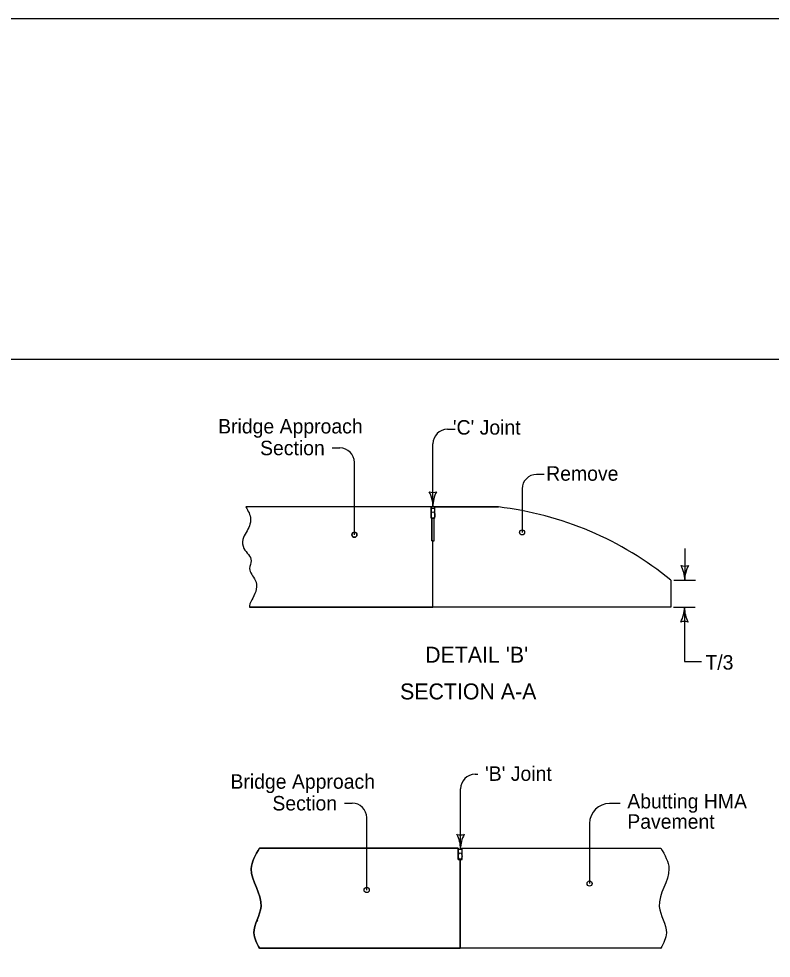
# Model space of a CAD drawing. Extents: x -2135039 to -2131695, y -2139150 to -2136566.
# Drawn here: x -2133963 to -2132926, y -2137862 to -2136566 of the extents above; entities that cross this region are included whole.
import ezdxf

# ---------------------------------------------------------------- set-up
doc = ezdxf.new("R2010")
doc.units = 0
for name, color, linetype in [('dsnCellElements', 7, 'Continuous'), ('dsnDOTLogo', 7, 'Continuous'), ('Level 1', 7, 'Continuous'), ('Level 2', 7, 'Continuous'), ('Level 3', 7, 'Continuous')]:
    doc.layers.add(name, color=color, linetype=linetype)

msp = doc.modelspace()

# ---------------------------------------------------------------- linework, layer by layer
at = {"layer": 'dsnCellElements'}
for centre in [(-2133483.7, -2137768.3), (-2133176.4, -2137759.4)]:
    msp.add_circle(centre, 3.54, dxfattribs=at)
at = {"layer": 'dsnDOTLogo'}
msp.add_lwpolyline([(-2135038.9, -2139150.4), (-2131694.9, -2139150.4), (-2131694.9, -2136566.4), (-2135038.9, -2136566.4)], close=True, dxfattribs=at)
at = {"layer": 'Level 1'}
msp.add_lwpolyline([(-2134934.4, -2137035.9), (-2131799.4, -2137035.9), (-2131799.4, -2139045.9), (-2134934.4, -2139045.9)], close=True, dxfattribs=at)
at = {"layer": 'Level 2'}
for p, q in [((-2133372.4, -2137132.8), (-2133361.7, -2137132.8)), ((-2133392.4, -2137239.3), (-2133392.4, -2137152.8)), ((-2133531.5, -2137158.4), (-2133520.7, -2137158.4)), ((-2133500.7, -2137278.2), (-2133500.7, -2137178.4)), ((-2133238.9, -2137195), (-2133249.4, -2137195)), ((-2133269.4, -2137215), (-2133269.4, -2137274.9)), ((-2133302.1, -2137239.9), (-2133650.3, -2137239.9)), ((-2133395, -2137239.9), (-2133395, -2137255.5)), ((-2133395, -2137241.5), (-2133389.7, -2137241.5)), ((-2133389.7, -2137255.5), (-2133389.7, -2137239.9)), ((-2133389.7, -2137239.9), (-2133302.1, -2137239.9)), ((-2133395, -2137255.5), (-2133390.6, -2137255.5)), ((-2133394.1, -2137255.5), (-2133395, -2137255.5)), ((-2133394.1, -2137255.5), (-2133394.1, -2137286.5)), ((-2133394.1, -2137286.5), (-2133394.1, -2137255.5)), ((-2133389.7, -2137255.5), (-2133390.6, -2137255.5)), ((-2133390.6, -2137286.5), (-2133390.6, -2137255.5)), ((-2133394.1, -2137286.5), (-2133392.3, -2137286.5)), ((-2133392.3, -2137286.5), (-2133394.1, -2137286.5)), ((-2133392.3, -2137378.2), (-2133392.3, -2137286.5)), ((-2133392.3, -2137286.5), (-2133390.6, -2137286.5)), ((-2133045.2, -2137297.1), (-2133045.2, -2137340.9)), ((-2133064.2, -2137340.9), (-2133064.2, -2137378.3)), ((-2133060.2, -2137340.9), (-2133030.2, -2137340.9)), ((-2133396.5, -2137378.2), (-2133645.1, -2137378.2)), ((-2133645.1, -2137378.2), (-2133396.5, -2137378.2)), ((-2133064.2, -2137378.2), (-2133396.5, -2137378.2)), ((-2133396.5, -2137378.2), (-2133392.3, -2137378.2)), ((-2133396.5, -2137378.2), (-2133392.3, -2137378.2)), ((-2133060.6, -2137378.3), (-2133030.6, -2137378.3)), ((-2133045.6, -2137378.3), (-2133045.6, -2137452.9)), ((-2133045.6, -2137452.9), (-2133022.1, -2137452.9)), ((-2133334.3, -2137608.7), (-2133330.4, -2137608.7)), ((-2133354.3, -2137711.8), (-2133354.3, -2137628.7)), ((-2133514.5, -2137648.5), (-2133503.7, -2137648.5)), ((-2133134.1, -2137649), (-2133148.7, -2137649)), ((-2133483.7, -2137768.3), (-2133483.7, -2137668.5)), ((-2133176.4, -2137676.6), (-2133176.4, -2137759.4)), ((-2133631.4, -2137710.4), (-2133357.4, -2137710.4)), ((-2133595.4, -2137710.4), (-2133631.4, -2137710.4)), ((-2133357.4, -2137710.4), (-2133357.4, -2137726)), ((-2133357.4, -2137712.1), (-2133352.2, -2137712.1)), ((-2133352.2, -2137726), (-2133352.2, -2137710.4)), ((-2133352.2, -2137710.4), (-2133078.2, -2137710.4)), ((-2133352.2, -2137711.7), (-2133351, -2137710.4)), ((-2133357.4, -2137726), (-2133354.8, -2137726)), ((-2133354.8, -2137726), (-2133357.4, -2137726)), ((-2133354.8, -2137726), (-2133352.2, -2137726)), ((-2133354.8, -2137848.7), (-2133354.8, -2137726)), ((-2133354.8, -2137726), (-2133354.8, -2137848.7)), ((-2133354.8, -2137805.1), (-2133354.8, -2137726)), ((-2133354.8, -2137726), (-2133354.8, -2137726)), ((-2133354.8, -2137831.7), (-2133354.8, -2137805.1)), ((-2133354.8, -2137805.1), (-2133354.8, -2137805.1)), ((-2133354.8, -2137831.7), (-2133354.8, -2137831.7)), ((-2133354.8, -2137848.7), (-2133631.4, -2137848.7)), ((-2133078.2, -2137848.7), (-2133354.8, -2137848.7)), ((-2133078.5, -2137848.7), (-2133077.8, -2137848))]:
    msp.add_line(p, q, dxfattribs=at)
for points in [[(-2133395, -2137239.9), (-2133500.7, -2137239.9), (-2133650.3, -2137239.9)], [(-2133395, -2137255.5), (-2133395, -2137241.5), (-2133395, -2137239.9)], [(-2133500.7, -2137274.7), (-2133500.7, -2137274.7)], [(-2133392.3, -2137378.2), (-2133392.3, -2137376.7), (-2133392.3, -2137368.3), (-2133392.3, -2137359.8), (-2133392.3, -2137351.3), (-2133392.3, -2137342.8), (-2133392.3, -2137334.3), (-2133392.3, -2137325.8), (-2133392.3, -2137317.3), (-2133392.3, -2137308.9), (-2133392.3, -2137300.4), (-2133392.3, -2137291.9), (-2133392.3, -2137286.5)], [(-2133595.4, -2137710.4), (-2133595.4, -2137710.4)], [(-2133546.9, -2137710.4), (-2133551.4, -2137710.4), (-2133593.7, -2137710.4)], [(-2133593.7, -2137710.4), (-2133593.7, -2137710.4)], [(-2133546.9, -2137710.4), (-2133546.9, -2137710.4)], [(-2133357.4, -2137710.4), (-2133414.3, -2137710.4), (-2133483.7, -2137710.4), (-2133545.2, -2137710.4)], [(-2133545.2, -2137710.4), (-2133545.2, -2137710.4)], [(-2133414.3, -2137710.4), (-2133414.3, -2137710.7)], [(-2133357.4, -2137726), (-2133357.4, -2137712.1), (-2133357.4, -2137710.4)], [(-2133354.8, -2137805.1), (-2133354.8, -2137805.1)], [(-2133354.8, -2137805.1), (-2133354.8, -2137805.1)], [(-2133354.8, -2137805.1), (-2133354.8, -2137805.1)], [(-2133354.8, -2137805.1), (-2133354.8, -2137805.1)], [(-2133633.8, -2137810.3), (-2133636.2, -2137812.9)], [(-2133354.8, -2137831.7), (-2133354.8, -2137831.7)], [(-2133354.8, -2137831.7), (-2133354.8, -2137831.7)], [(-2133354.8, -2137848), (-2133354.8, -2137848), (-2133354.8, -2137831.7)], [(-2133354.8, -2137831.7), (-2133354.8, -2137831.7)], [(-2133354.8, -2137831.7), (-2133354.8, -2137831.7)], [(-2133631.4, -2137848.7), (-2133415, -2137848.7), (-2133356.3, -2137848.7)], [(-2133356.3, -2137848.7), (-2133356.3, -2137848.7)]]:
    msp.add_lwpolyline(points, dxfattribs=at)
for centre, radius in [((-2133269.4, -2137274.9), 3.5), ((-2133500.7, -2137278.2), 3.5), ((-2133483.7, -2137768.3), 3.54)]:
    msp.add_circle(centre, radius, dxfattribs=at)
for centre, radius, start, end in [((-2133372.4, -2137152.8), 20, 90, 180), ((-2133520.7, -2137178.4), 20, 0, 90), ((-2133249.4, -2137215), 20, 90, 180), ((-2133392.4, -2137203.1), 16.7, 252.2666, 287.7333), ((-2133435.6, -2137239.3), 43.2, 360, 28.0725), ((-2133349.3, -2137239.3), 43.2, 151.9275, 180), ((-2133355.5, -2137696.2), 459.4, 50.6582, 83.3286), ((-2133500.7, -2137278.2), 3.5, 90.0901, 90), ((-2133045.2, -2137304.7), 16.7, 252.2666, 287.7333), ((-2133088.4, -2137340.9), 43.2, 360, 28.0725), ((-2133002, -2137340.9), 43.2, 151.9275, 180), ((-2133088.8, -2137378.3), 43.2, 331.9275, 360), ((-2133002.4, -2137378.3), 43.2, 180, 208.0725), ((-2133045.6, -2137414.5), 16.7, 72.2666, 107.7334), ((-2133334.3, -2137628.7), 20, 90, 180), ((-2133503.7, -2137668.5), 20, 0, 90), ((-2133148.7, -2137676.6), 27.7, 90, 180), ((-2133354.3, -2137675.6), 16.7, 252.2666, 287.7333), ((-2133397.5, -2137711.8), 43.2, 360, 28.0725), ((-2133311.1, -2137711.8), 43.2, 151.9275, 180)]:
    msp.add_arc(centre, radius, start, end, dxfattribs=at)
for centre in [(-2133392.3, -2137251.2), (-2133354.8, -2137721.6)]:
    msp.add_ellipse(centre, major_axis=(0, 4.37), ratio=0.6, dxfattribs=at)
for points in [[(-2133650.3, -2137239.9), (-2133643.7, -2137256.4), (-2133649.8, -2137274.9), (-2133654.4, -2137284.8), (-2133652.9, -2137297.1), (-2133642.9, -2137314), (-2133645.2, -2137324.8), (-2133637.3, -2137340.9), (-2133640.6, -2137365.5), (-2133645.2, -2137376.2), (-2133645.1, -2137378.2)], [(-2133650.3, -2137239.9), (-2133643.7, -2137256.4), (-2133649.8, -2137274.9), (-2133654.4, -2137284.8), (-2133652.9, -2137297.1), (-2133642.9, -2137314), (-2133645.2, -2137324.8), (-2133637.3, -2137340.9), (-2133640.6, -2137365.5), (-2133645.2, -2137376.2), (-2133645.1, -2137378.2)], [(-2133631.4, -2137848.7), (-2133639.2, -2137827.6), (-2133629.4, -2137791), (-2133642.8, -2137739.2), (-2133631.4, -2137710.4)], [(-2133631.4, -2137710.4), (-2133642.8, -2137739.2), (-2133629.4, -2137791), (-2133639.2, -2137827.6), (-2133631.4, -2137848.7)], [(-2133078.2, -2137710.4), (-2133066.9, -2137739.2), (-2133080.3, -2137791), (-2133070.4, -2137827.6), (-2133078.2, -2137848.7)]]:
    msp.add_spline(points, degree=3, dxfattribs=at)
for points, degree in [([(-2133593.7, -2137710.4), (-2133594.2, -2137710.5), (-2133594.8, -2137710.5), (-2133595.4, -2137710.4)], 2), ([(-2133545.2, -2137710.4), (-2133545.7, -2137710.5), (-2133546.3, -2137710.5), (-2133546.9, -2137710.4)], 2), ([(-2133356.3, -2137848.7), (-2133354.8, -2137848.7), (-2133354.8, -2137848.7), (-2133354.8, -2137848.7), (-2133354.8, -2137848)], 3)]:
    msp.add_open_spline(points, degree=degree, dxfattribs=at)

# ---------------------------------------------------------------- texts
at = {"layer": 'Level 3'}
for s, height, p in [('Bridge Approach', 20, (-2133688.5, -2137138.5)), ("'C' Joint", 20, (-2133364.9, -2137140.1)), ('Section', 20, (-2133630.7, -2137168.5)), ('Remove', 20, (-2133236.2, -2137203.7)), ("DETAIL 'B'", 22, (-2133403.1, -2137454.7)), ('T/3', 20, (-2133016.7, -2137464.3)), ('SECTION A-A', 22, (-2133437.7, -2137505.4)), ("'B' Joint", 20, (-2133320.5, -2137617.7)), ('Bridge Approach', 20, (-2133671.5, -2137628.6)), ('Abutting HMA', 20, (-2133124.4, -2137655.8)), ('Section', 20, (-2133613.7, -2137658.6)), ('Pavement', 20, (-2133124.4, -2137683.8))]:
    msp.add_text(s, height=height, dxfattribs=at).set_placement(p)

doc.saveas('drawing.dxf')
